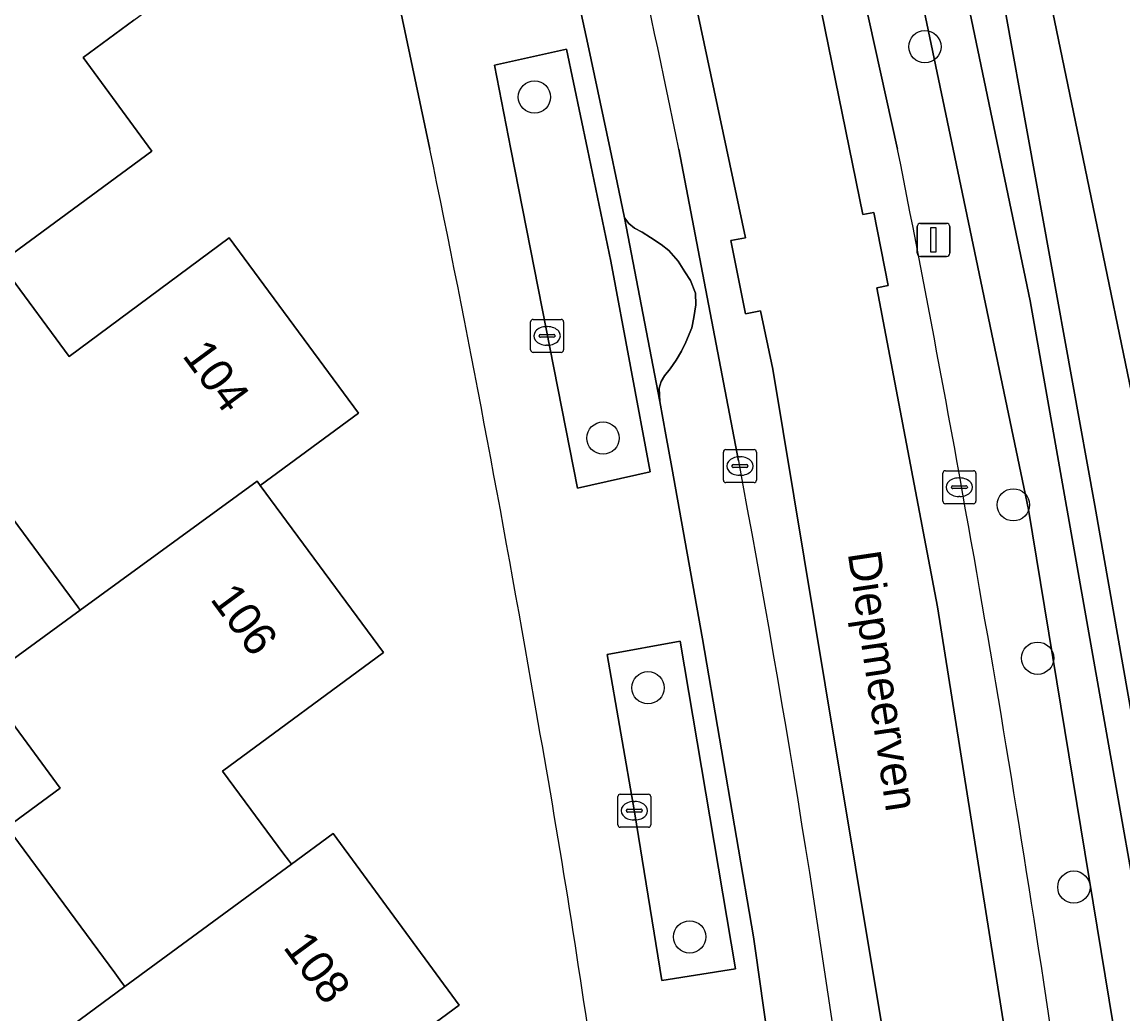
# Model space of a CAD drawing. Extents: x 163426 to 164192, y 380329 to 381641.
# Drawn here: x 163921.81 to 163955.16, y 381223.81 to 381253.85 of the extents above; entities that cross this region are included whole.
import ezdxf

# ---------------------------------------------------------------- set-up
doc = ezdxf.new("R2010")
doc.units = 0
for name, color, linetype in [('IMGEO_Boom', 7, 'Continuous'), ('IMGEO_Erf', 7, 'Continuous'), ('IMGEO_Groenvoorziening', 7, 'Continuous'), ('IMGEO_Kolk', 7, 'Continuous'), ('IMGEO_Lichtmast', 7, 'Continuous'), ('IMGEO_Oever', 7, 'Continuous'), ('IMGEO_Openbare_ruimte_label', 7, 'Continuous'), ('IMGEO_Pand', 7, 'Continuous'), ('IMGEO_Pand_nummerreeks', 7, 'Continuous'), ('IMGEO_Parkeervlak_open', 7, 'Continuous'), ('IMGEO_Rijbaan_lokaal_gesloten', 7, 'Continuous'), ('IMGEO_Verkeerseiland_open', 7, 'Continuous'), ('IMGEO_Voetpad_open', 7, 'Continuous'), ('IMGEO_Waterloop', 7, 'Continuous')]:
    doc.layers.add(name, color=color, linetype=linetype)

msp = doc.modelspace()

# ---------------------------------------------------------------- linework, layer by layer
at = {"layer": 'IMGEO_Boom'}
for centre in [(163949.16, 381253.1), (163937.333, 381251.576), (163939.411, 381241.248), (163951.839, 381239.226), (163952.575, 381234.582), (163940.773, 381233.686), (163953.673, 381227.649), (163942.035, 381226.141)]:
    msp.add_circle(centre, 0.489, dxfattribs=at)
at = {"layer": 'IMGEO_Erf'}
for points in [[(164001.617, 381299.59), (164000, 381299.079), (163946.357, 381282.135), (163946.949, 381280.126), (163950.911, 381264.377), (163953.894, 381250), (163955.908, 381240.291), (163959.527, 381217.462), (163960.076, 381214.403), (163973.754, 381216.166)], [(163925.203, 381253.905), (163923.664, 381252.776), (163925.746, 381249.938), (163921.142, 381246.559)], [(163934.167, 381250), (163933.3, 381254.106)], [(163921.349, 381246.279), (163923.241, 381243.723), (163928.087, 381247.31), (163932.004, 381242.003), (163929.027, 381239.809), (163932.757, 381234.753), (163927.885, 381231.164), (163929.745, 381228.65), (163929.881, 381228.466), (163929.973, 381228.341), (163931.237, 381229.27), (163935.058, 381224.076), (163930.198, 381220.5), (163933.192, 381216.427), (163933.327, 381215.334), (163930.724, 381212.101), (163925.359, 381209.706), (163922.998, 381208.373), (163920.026, 381212.394)], [(163919.557, 381213.029), (163924.967, 381217.028), (163923.674, 381218.778), (163925.279, 381219.965), (163922.918, 381223.159), (163924.929, 381224.636), (163924.829, 381224.772), (163924.62, 381225.054), (163921.364, 381229.46), (163922.97, 381230.647), (163920.592, 381233.864), (163923.577, 381236.038), (163923.501, 381236.141), (163923.394, 381236.286), (163921.229, 381239.216)]]:
    msp.add_lwpolyline(points, dxfattribs=at)
for centre, radius, start, end in [((163443.56, 381148.488), 500.999, 9.7504, 11.6902), ((163632.552, 381178.37), 309.687, 8.10941, 10.22327)]:
    msp.add_arc(centre, radius, start, end, dxfattribs=at)
at = {"layer": 'IMGEO_Groenvoorziening'}
for points in [[(163955.838, 381217.536), (163952.296, 381239.088), (163950.014, 381250), (163947.625, 381261.424), (163943.73, 381277.607), (163943.768, 381279.495), (163944.591, 381279.658), (163946.949, 381280.126), (163946.357, 381282.135)], [(163943.145, 381278.24), (163943.229, 381277.838), (163941.823, 381277.416), (163942.486, 381274.934), (163944.765, 381266.145), (163948.335, 381250)]]:
    msp.add_lwpolyline(points, dxfattribs=at)
for points in [[(163938.639, 381239.731), (163940.84, 381240.228), (163939.646, 381246.606), (163938.938, 381250), (163938.305, 381253.03), (163936.125, 381252.542), (163936.622, 381250), (163937.567, 381245.174)], [(163941.191, 381224.82), (163943.423, 381225.172), (163941.75, 381235.096), (163939.539, 381234.696), (163940.366, 381229.927)]]:
    msp.add_lwpolyline(points, close=True, dxfattribs=at)
msp.add_arc((163385.867, 381138.283), 573.456, 8.143357, 11.233859, dxfattribs=at)
at = {"layer": 'IMGEO_Kolk'}
for p, q in [((163937.292, 381244.843), (163938.144, 381244.843)), ((163937.217, 381243.917), (163937.217, 381244.769)), ((163937.705, 381244.623), (163937.73, 381244.623)), ((163938.218, 381244.769), (163938.218, 381243.917)), ((163937.476, 381244.337), (163937.476, 381244.349)), ((163937.914, 381244.3), (163937.516, 381244.3)), ((163937.519, 381244.386), (163937.917, 381244.386)), ((163937.96, 381244.349), (163937.96, 381244.337)), ((163938.144, 381243.843), (163937.292, 381243.843)), ((163937.728, 381244.063), (163937.703, 381244.063)), ((163943.057, 381239.974), (163943.057, 381240.826)), ((163943.132, 381240.9), (163943.984, 381240.9)), ((163944.058, 381240.826), (163944.058, 381239.974)), ((163943.545, 381240.68), (163943.57, 381240.68)), ((163943.316, 381240.394), (163943.316, 381240.406)), ((163943.754, 381240.357), (163943.356, 381240.357)), ((163943.359, 381240.443), (163943.757, 381240.443)), ((163943.8, 381240.406), (163943.8, 381240.394)), ((163949.705, 381239.334), (163949.705, 381240.186)), ((163949.78, 381240.26), (163950.632, 381240.26)), ((163950.706, 381240.186), (163950.706, 381239.334)), ((163943.984, 381239.9), (163943.132, 381239.9)), ((163943.568, 381240.12), (163943.543, 381240.12)), ((163950.193, 381240.04), (163950.218, 381240.04)), ((163949.964, 381239.754), (163949.964, 381239.766)), ((163950.402, 381239.717), (163950.004, 381239.717)), ((163950.007, 381239.803), (163950.405, 381239.803)), ((163950.448, 381239.766), (163950.448, 381239.754)), ((163950.632, 381239.26), (163949.78, 381239.26)), ((163950.216, 381239.48), (163950.191, 381239.48)), ((163939.858, 381229.537), (163939.858, 381230.389)), ((163939.933, 381230.463), (163940.785, 381230.463)), ((163940.346, 381230.243), (163940.371, 381230.243)), ((163940.859, 381230.389), (163940.859, 381229.537)), ((163940.117, 381229.957), (163940.117, 381229.969)), ((163940.555, 381229.92), (163940.157, 381229.92)), ((163940.16, 381230.006), (163940.558, 381230.006)), ((163940.601, 381229.969), (163940.601, 381229.957)), ((163940.369, 381229.683), (163940.344, 381229.683)), ((163940.785, 381229.463), (163939.933, 381229.463))]:
    msp.add_line(p, q, dxfattribs=at)
for points in [[(163937.292, 381244.843), (163938.144, 381244.843)], [(163937.217, 381243.917), (163937.217, 381244.769)], [(163938.218, 381244.769), (163938.218, 381243.917)], [(163938.144, 381243.843), (163937.292, 381243.843)], [(163943.057, 381239.974), (163943.057, 381240.826)], [(163943.132, 381240.9), (163943.984, 381240.9)], [(163944.058, 381240.826), (163944.058, 381239.974)], [(163949.705, 381239.334), (163949.705, 381240.186)], [(163949.78, 381240.26), (163950.632, 381240.26)], [(163950.706, 381240.186), (163950.706, 381239.334)], [(163943.984, 381239.9), (163943.132, 381239.9)], [(163950.632, 381239.26), (163949.78, 381239.26)], [(163939.858, 381229.537), (163939.858, 381230.389)], [(163939.933, 381230.463), (163940.785, 381230.463)], [(163940.859, 381230.389), (163940.859, 381229.537)], [(163940.785, 381229.463), (163939.933, 381229.463)]]:
    msp.add_lwpolyline(points, dxfattribs=at)
for centre, radius, start, end in [((163937.294, 381244.767), 0.0765, 91.552, 178.448), ((163937.294, 381244.767), 0.0765, 91.552, 178.448), ((163938.142, 381244.767), 0.0765, 1.552, 88.448), ((163938.142, 381244.767), 0.0765, 1.552, 88.448), ((163937.516, 381244.346), 0.0403, 85.8775, 175.7526), ((163937.513, 381244.336), 0.0366, 178.938, 274.7102), ((163937.917, 381244.343), 0.043, 264.8664, 352.4533), ((163937.921, 381244.348), 0.0386, 1.7309, 96.639), ((163937.294, 381243.919), 0.0765, 181.552, 268.448), ((163937.294, 381243.919), 0.0765, 181.552, 268.448), ((163938.142, 381243.919), 0.0765, 271.552, 358.448), ((163938.142, 381243.919), 0.0765, 271.552, 358.448), ((163943.134, 381240.824), 0.0765, 91.552, 178.448), ((163943.134, 381240.824), 0.0765, 91.552, 178.448), ((163943.982, 381240.824), 0.0765, 1.552, 88.448), ((163943.982, 381240.824), 0.0765, 1.552, 88.448), ((163943.356, 381240.403), 0.0403, 85.8775, 175.7526), ((163943.353, 381240.393), 0.0366, 178.938, 274.7102), ((163943.757, 381240.4), 0.043, 264.8664, 352.4533), ((163943.761, 381240.405), 0.0386, 1.7309, 96.639), ((163949.782, 381240.184), 0.0765, 91.552, 178.448), ((163949.782, 381240.184), 0.0765, 91.552, 178.448), ((163950.63, 381240.184), 0.0765, 1.552, 88.448), ((163950.63, 381240.184), 0.0765, 1.552, 88.448), ((163943.134, 381239.976), 0.0765, 181.552, 268.448), ((163943.134, 381239.976), 0.0765, 181.552, 268.448), ((163943.982, 381239.976), 0.0765, 271.552, 358.448), ((163943.982, 381239.976), 0.0765, 271.552, 358.448), ((163950.004, 381239.763), 0.0403, 85.8775, 175.7526), ((163950.001, 381239.753), 0.0366, 178.938, 274.7102), ((163950.405, 381239.76), 0.043, 264.8664, 352.4533), ((163950.409, 381239.765), 0.0386, 1.7309, 96.639), ((163949.782, 381239.336), 0.0765, 181.552, 268.448), ((163949.782, 381239.336), 0.0765, 181.552, 268.448), ((163950.63, 381239.336), 0.0765, 271.552, 358.448), ((163950.63, 381239.336), 0.0765, 271.552, 358.448), ((163939.935, 381230.387), 0.0765, 91.552, 178.448), ((163939.935, 381230.387), 0.0765, 91.552, 178.448), ((163940.783, 381230.387), 0.0765, 1.552, 88.448), ((163940.783, 381230.387), 0.0765, 1.552, 88.448), ((163940.157, 381229.966), 0.0403, 85.8775, 175.7526), ((163940.154, 381229.956), 0.0366, 178.938, 274.7102), ((163940.558, 381229.963), 0.043, 264.8664, 352.4533), ((163940.562, 381229.968), 0.0386, 1.7309, 96.639), ((163939.935, 381229.539), 0.0765, 181.552, 268.448), ((163939.935, 381229.539), 0.0765, 181.552, 268.448), ((163940.783, 381229.539), 0.0765, 271.552, 358.448), ((163940.783, 381229.539), 0.0765, 271.552, 358.448)]:
    msp.add_arc(centre, radius, start, end, dxfattribs=at)
for centre, major_axis, ratio, start_param, end_param in [((163937.704, 381244.343), (-0.387, 0.002), 0.722429, 4.712389, 7.853982), ((163937.729, 381244.343), (-0.39, 0.002), 0.717154, 1.570796, 4.712389), ((163943.544, 381240.4), (-0.387, 0.002), 0.722429, 4.712389, 7.853982), ((163943.569, 381240.4), (-0.39, 0.002), 0.717154, 1.570796, 4.712389), ((163950.192, 381239.76), (-0.387, 0.002), 0.722429, 4.712389, 7.853982), ((163950.217, 381239.76), (-0.39, 0.002), 0.717154, 1.570796, 4.712389), ((163940.345, 381229.963), (-0.387, 0.002), 0.722429, 4.712389, 7.853982), ((163940.37, 381229.963), (-0.39, 0.002), 0.717154, 1.570796, 4.712389)]:
    msp.add_ellipse(centre, major_axis=major_axis, ratio=ratio, start_param=start_param, end_param=end_param, dxfattribs=at)
at = {"layer": 'IMGEO_Lichtmast'}
for p, q in [((163948.924, 381246.851), (163948.924, 381247.651)), ((163948.924, 381247.651), (163948.924, 381246.851)), ((163949.024, 381247.751), (163949.814, 381247.751)), ((163949.814, 381247.751), (163949.024, 381247.751)), ((163949.914, 381247.651), (163949.914, 381246.851)), ((163949.914, 381246.851), (163949.914, 381247.651)), ((163949.814, 381246.751), (163949.024, 381246.751)), ((163949.024, 381246.751), (163949.814, 381246.751))]:
    msp.add_line(p, q, dxfattribs=at)
msp.add_lwpolyline([(163949.344, 381247.626), (163949.494, 381247.626), (163949.494, 381246.876), (163949.344, 381246.876), (163949.344, 381247.626)], dxfattribs=at)
for centre, start, end in [((163949.024, 381247.651), 90, 180), ((163949.024, 381247.651), 90, 180), ((163949.814, 381247.651), 0, 90), ((163949.814, 381247.651), 360, 90), ((163949.024, 381246.851), 180, 270), ((163949.024, 381246.851), 180, 270), ((163949.814, 381246.851), 270, 0), ((163949.814, 381246.851), 270, 0)]:
    msp.add_arc(centre, 0.1, start, end, dxfattribs=at)
at = {"layer": 'IMGEO_Oever'}
for points in [[(163950.911, 381264.377), (163946.949, 381280.126), (163944.591, 381279.658), (163943.768, 381279.495), (163943.73, 381277.607), (163947.625, 381261.424), (163950.014, 381250), (163952.296, 381239.088), (163955.838, 381217.536)], [(163957.309, 381216.003), (163957.474, 381215.976), (163957.642, 381215.964), (163957.809, 381215.967), (163957.976, 381215.985), (163958.14, 381216.018), (163958.301, 381216.066), (163958.457, 381216.127), (163958.606, 381216.202), (163958.749, 381216.291), (163958.883, 381216.391), (163959.007, 381216.503), (163959.121, 381216.626), (163959.223, 381216.759), (163959.314, 381216.9), (163959.391, 381217.049), (163959.455, 381217.204), (163959.504, 381217.364), (163959.527, 381217.462), (163955.908, 381240.291), (163953.894, 381250), (163950.911, 381264.377)]]:
    msp.add_lwpolyline(points, dxfattribs=at)
msp.add_lwpolyline([(163945.788, 381278.484), (163951.599, 381254.151), (163954.309, 381239.202), (163957.143, 381223.063), (163957.944, 381217.087), (163957.04, 381216.995), (163955.931, 381225.126), (163954.566, 381232.837), (163952.348, 381245.404), (163949.802, 381257.601), (163947.42, 381267.868), (163944.766, 381278.235)], close=True, dxfattribs=at)
at = {"layer": 'IMGEO_Pand'}
for points in [[(163923.541, 381260.701), (163916.694, 381255.744), (163919.089, 381252.478), (163917.477, 381251.296), (163918.427, 381250), (163920.319, 381247.421), (163920.924, 381246.596), (163921.018, 381246.468), (163921.142, 381246.559), (163925.746, 381249.938), (163923.664, 381252.776), (163925.203, 381253.905), (163928.858, 381256.586), (163925.042, 381261.788)], [(163921.142, 381246.559), (163921.018, 381246.468), (163916.069, 381242.837), (163919.623, 381238.029), (163921.229, 381239.216), (163923.394, 381236.286), (163923.501, 381236.141), (163923.577, 381236.038), (163928.932, 381239.938), (163929.027, 381239.809), (163932.004, 381242.003), (163928.087, 381247.31), (163923.241, 381243.723), (163921.349, 381246.279), (163921.255, 381246.406)], [(163929.027, 381239.809), (163928.932, 381239.938), (163923.577, 381236.038), (163920.592, 381233.864), (163922.97, 381230.647), (163921.364, 381229.46), (163924.62, 381225.054), (163924.829, 381224.772), (163924.929, 381224.636), (163929.973, 381228.341), (163929.881, 381228.466), (163929.745, 381228.65), (163927.885, 381231.164), (163932.757, 381234.753)], [(163930.198, 381220.5), (163935.058, 381224.076), (163931.237, 381229.27), (163929.973, 381228.341), (163924.929, 381224.636), (163922.918, 381223.159), (163925.279, 381219.965), (163923.674, 381218.778), (163924.967, 381217.028), (163919.557, 381213.029), (163920.026, 381212.394), (163922.998, 381208.373), (163925.359, 381209.706), (163930.724, 381212.101), (163933.327, 381215.334), (163933.192, 381216.427)]]:
    msp.add_lwpolyline(points, close=True, dxfattribs=at)
at = {"layer": 'IMGEO_Parkeervlak_open'}
for points in [[(163937.51, 381259.832), (163938.955, 381253.175), (163939.627, 381250), (163939.835, 381248.988), (163940.062, 381247.913), (163940.194, 381247.75), (163940.368, 381247.607), (163940.597, 381247.483), (163940.853, 381247.321), (163941.171, 381247.114), (163941.4, 381246.924), (163941.684, 381246.607), (163941.891, 381246.283), (163942.058, 381246.015), (163942.215, 381245.638), (163942.224, 381245.288), (163942.162, 381244.903), (163942.101, 381244.584), (163941.918, 381244.152), (163941.79, 381243.879), (163941.628, 381243.606), (163941.449, 381243.349), (163941.275, 381243.128), (163941.176, 381242.958), (163941.114, 381242.759), (163941.127, 381242.354), (163941.313, 381241.342), (163941.491, 381240.359), (163942.427, 381235.164), (163943.966, 381226.145), (163944.027, 381225.716), (163944.882, 381219.713)], [(163943.519, 381240.555), (163941.708, 381250)]]:
    msp.add_lwpolyline(points, dxfattribs=at)
for centre, radius, start, end in [((163522.519, 381163.934), 427.933, 11.60247, 13.52023), ((163518.613, 381160.815), 432.324, 7.47236, 10.62875)]:
    msp.add_arc(centre, radius, start, end, dxfattribs=at)
at = {"layer": 'IMGEO_Rijbaan_lokaal_gesloten'}
for points in [[(163947.265, 381217.038), (163948.882, 381217.269), (163946.144, 381233.78), (163944.552, 381243.335), (163944.183, 381245.1), (163943.726, 381245.01), (163943.287, 381247.227), (163943.722, 381247.313), (163942.098, 381254.961), (163933.228, 381290.176), (163930.68, 381299.334), (163925.802, 381316.596), (163925.405, 381316.489), (163924.817, 381318.679), (163925.185, 381318.778), (163921.907, 381330.645), (163913.697, 381359.629), (163912.249, 381359.295), (163912.307, 381359.162), (163912.358, 381358.996)], [(163933.228, 381290.176), (163942.098, 381254.961), (163943.722, 381247.313), (163943.287, 381247.227), (163943.726, 381245.01), (163944.183, 381245.1), (163944.552, 381243.335), (163946.144, 381233.78), (163948.882, 381217.269), (163947.265, 381217.038), (163949.305, 381200.709), (163949.328, 381200.396), (163949.339, 381200.263), (163951.02, 381200.319), (163951.421, 381194.676), (163953.356, 381172.452), (163955.532, 381147.148), (163954.94, 381147.096), (163955.139, 381144.825), (163955.706, 381144.875), (163956.194, 381138.505), (163958.336, 381112.694)], [(163953.779, 381217.501), (163953.683, 381218.285), (163953.57, 381219.255), (163952.161, 381219.119), (163951.806, 381221.884), (163949.541, 381236.14), (163947.702, 381245.797), (163948.052, 381245.866), (163947.613, 381248.083), (163947.279, 381248.017), (163944.361, 381262.334), (163940.492, 381277.062), (163941.823, 381277.416), (163941.502, 381278.63), (163938.317, 381290.329)], [(163948.335, 381250), (163944.765, 381266.145), (163942.486, 381274.934), (163941.823, 381277.416), (163940.492, 381277.062), (163944.361, 381262.334), (163947.279, 381248.017), (163947.613, 381248.083), (163948.052, 381245.866), (163947.702, 381245.797), (163949.541, 381236.14), (163951.806, 381221.884), (163952.161, 381219.119), (163953.57, 381219.255), (163953.54, 381219.513)], [(163941.708, 381250), (163943.519, 381240.555)]]:
    msp.add_lwpolyline(points, dxfattribs=at)
for centre, radius, start, end in [((163522.519, 381163.934), 427.933, 11.60247, 13.52023), ((163385.867, 381138.283), 573.456, 8.143357, 11.233859), ((163518.613, 381160.815), 432.324, 7.47236, 10.62875)]:
    msp.add_arc(centre, radius, start, end, dxfattribs=at)
at = {"layer": 'IMGEO_Verkeerseiland_open'}
msp.add_lwpolyline([(163941.127, 381242.354), (163941.114, 381242.759), (163941.176, 381242.958), (163941.275, 381243.128), (163941.449, 381243.349), (163941.628, 381243.606), (163941.79, 381243.879), (163941.918, 381244.152), (163942.101, 381244.584), (163942.162, 381244.903), (163942.224, 381245.288), (163942.215, 381245.638), (163942.058, 381246.015), (163941.891, 381246.283), (163941.684, 381246.607), (163941.4, 381246.924), (163941.171, 381247.114), (163940.853, 381247.321), (163940.597, 381247.483), (163940.368, 381247.607), (163940.194, 381247.75), (163940.062, 381247.913)], close=True, dxfattribs=at)
at = {"layer": 'IMGEO_Voetpad_open'}
for points in [[(163944.882, 381219.713), (163944.027, 381225.716), (163943.966, 381226.145), (163942.427, 381235.164), (163941.491, 381240.359), (163941.313, 381241.342), (163941.127, 381242.354), (163940.062, 381247.913), (163939.835, 381248.988), (163939.627, 381250), (163938.955, 381253.175), (163937.51, 381259.832), (163936.359, 381264.784), (163935.892, 381266.688), (163934.592, 381271.826), (163933.019, 381277.636), (163931.635, 381282.748)], [(163933.3, 381254.106), (163934.167, 381250)]]:
    msp.add_lwpolyline(points, dxfattribs=at)
for points in [[(163938.305, 381253.03), (163938.938, 381250), (163939.646, 381246.606), (163940.84, 381240.228), (163938.639, 381239.731), (163937.567, 381245.174), (163936.622, 381250), (163936.125, 381252.542)], [(163941.75, 381235.096), (163943.423, 381225.172), (163941.191, 381224.82), (163940.366, 381229.927), (163939.539, 381234.696)]]:
    msp.add_lwpolyline(points, close=True, dxfattribs=at)
for centre, radius, start, end in [((163443.56, 381148.488), 500.999, 9.7504, 11.6902), ((163632.552, 381178.37), 309.687, 8.10941, 10.22327)]:
    msp.add_arc(centre, radius, start, end, dxfattribs=at)
at = {"layer": 'IMGEO_Waterloop'}
msp.add_lwpolyline([(163945.788, 381278.484), (163944.766, 381278.235), (163947.42, 381267.868), (163949.802, 381257.601), (163952.348, 381245.404), (163954.566, 381232.837), (163955.931, 381225.126), (163957.04, 381216.995), (163957.944, 381217.087), (163957.143, 381223.063), (163954.309, 381239.202), (163951.599, 381254.151)], close=True, dxfattribs=at)

# ---------------------------------------------------------------- texts
at = {"layer": 'IMGEO_Openbare_ruimte_label'}
msp.add_text('Diepmeerven', height=1, rotation=278.4543, dxfattribs=at).set_placement((163946.822, 381237.761))
at = {"layer": 'IMGEO_Pand_nummerreeks'}
for s, rotation, p in [('104', 306.4284, (163926.642, 381243.744)), ('106', 306.417, (163927.488, 381236.369)), ('108', 306.3425, (163929.697, 381225.828))]:
    msp.add_text(s, height=1, rotation=rotation, dxfattribs=at).set_placement(p)

doc.saveas('drawing.dxf')
